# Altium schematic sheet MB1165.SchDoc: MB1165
size A3; DocumentNumber: MB1165; Revision: C.1; SheetNumber: 1; SheetTotal: 17; Project: STM32469I-EVAL
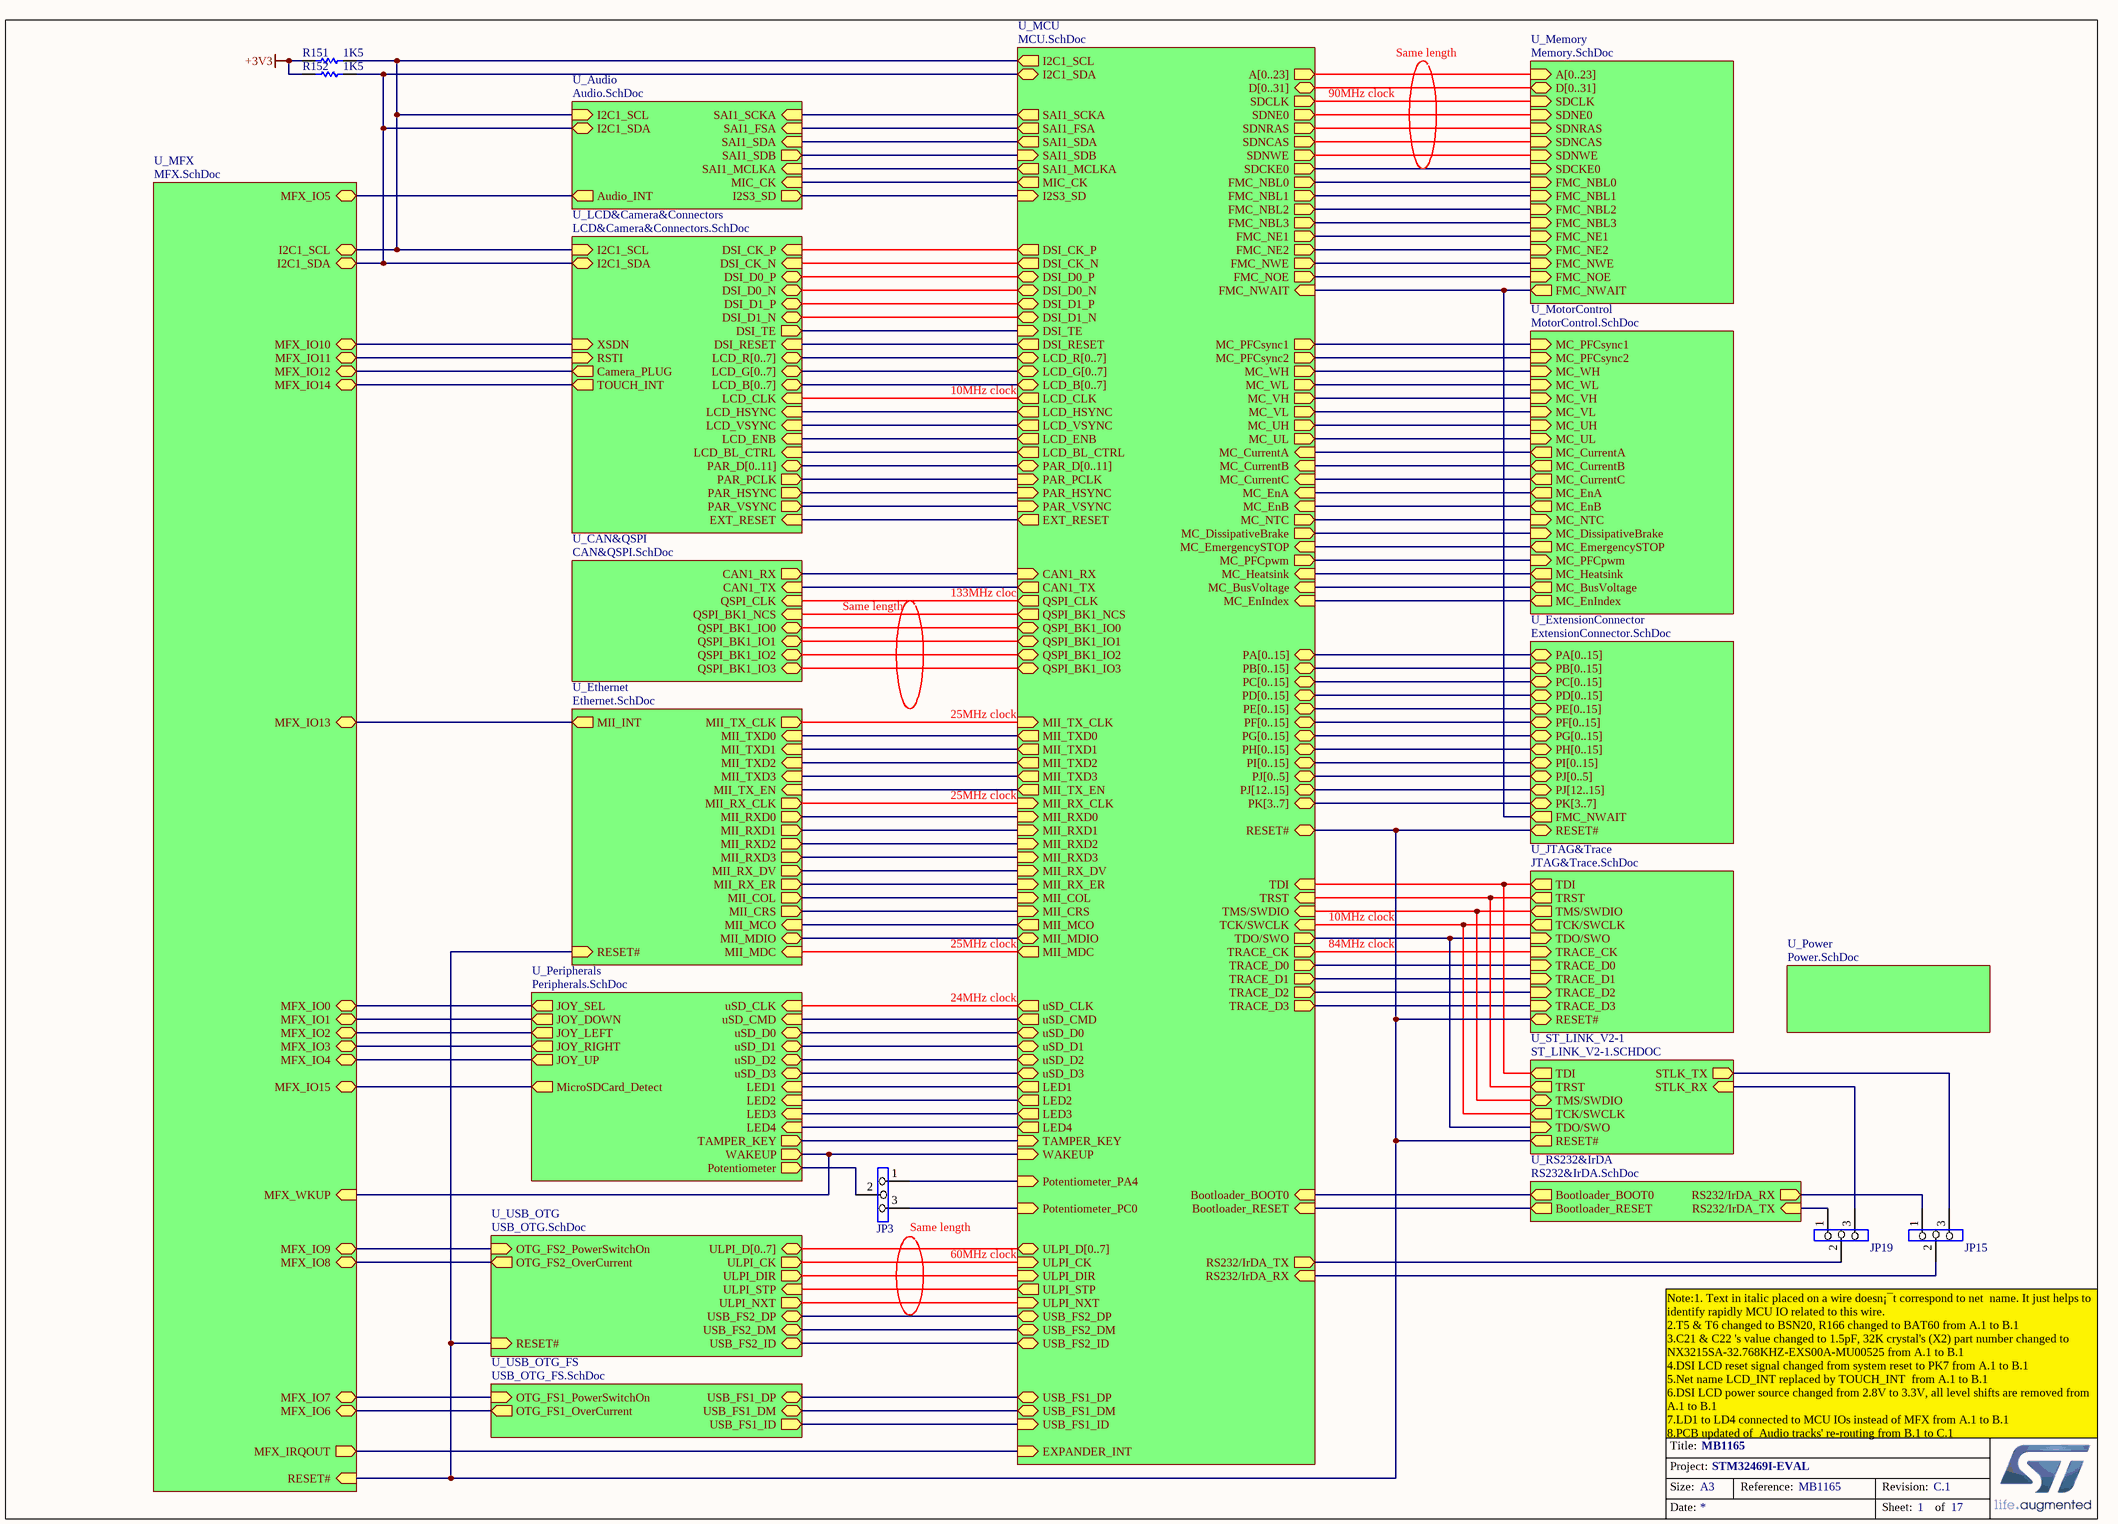
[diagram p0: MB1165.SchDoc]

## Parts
JP3  (no value)  [SIP3]
JP15  (no value)  [SIP3]
JP19  (no value)  [SIP3]
R151  1K5  [0603R]
R152  1K5  [0603R]

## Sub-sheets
U_Audio = Audio.SchDoc: SAI1_SCKA (in), SAI1_FSA (in), SAI1_SDA (in), SAI1_SDB (out), Audio_INT (out), I2C1_SDA (bidir), I2C1_SCL (in), SAI1_MCLKA (in), MIC_CK (in), I2S3_SD (out)
U_CAN&QSPI = CAN&QSPI.SchDoc: CAN1_TX (in), CAN1_RX (out), QSPI_BK1_IO0 (bidir), QSPI_BK1_IO3 (bidir), QSPI_BK1_IO2 (bidir), QSPI_BK1_IO1 (bidir), QSPI_CLK (in), QSPI_BK1_NCS (in)
U_Ethernet = Ethernet.SchDoc: MII_TXD0 (in), MII_TX_EN (in), MII_TX_CLK (out), MII_RXD0 (out), MII_RX_ER (out), MII_RX_DV (out), MII_RX_CLK (out), MII_COL (out), MII_CRS (out), MII_MDC (in), MII_MDIO (bidir), RESET# (in), MII_TXD1 (in), MII_TXD2 (in), MII_TXD3 (in), MII_RXD1 (out), MII_RXD2 (out), MII_RXD3 (out), MII_INT (out), MII_MCO (in)
U_ExtensionConnector = ExtensionConnector.SchDoc: PA[0..15] (bidir), PB[0..15] (bidir), PC[0..15] (bidir), PD[0..15] (bidir), PE[0..15] (bidir), PF[0..15] (bidir), PG[0..15] (bidir), PH[0..15] (bidir), PI[0..15] (bidir), RESET# (bidir), FMC_NWAIT (out), PJ[0..5] (bidir), PK[3..7] (bidir), PJ[12..15] (bidir)
U_JTAG&Trace = JTAG&Trace.SchDoc: TDI (out), RESET# (bidir), TRACE_D3 (in), TRACE_D2 (in), TRACE_D1 (in), TRACE_D0 (in), TRACE_CK (in), TRST (out), TMS/SWDIO (out), TCK/SWCLK (out), TDO/SWO (in)
U_LCD&Camera&Connectors = LCD&Camera&Connectors.SchDoc: LCD_R[0..7] (bidir), LCD_HSYNC (in), LCD_VSYNC (in), LCD_CLK (in), LCD_ENB (in), I2C1_SDA (bidir), I2C1_SCL (in), LCD_B[0..7] (bidir), LCD_G[0..7] (bidir), RSTI (in), XSDN (in), PAR_HSYNC (out), PAR_PCLK (out), PAR_VSYNC (out), PAR_D[0..11] (bidir), TOUCH_INT (out), Camera_PLUG (out), EXT_RESET (in), DSI_CK_P (in), DSI_CK_N (in), DSI_D0_P (bidir), DSI_D0_N (bidir), DSI_D1_P (bidir), DSI_D1_N (bidir), LCD_BL_CTRL (in), DSI_TE (out), DSI_RESET (in)
U_MCU = MCU.SchDoc: PA[0..15] (bidir), PB[0..15] (bidir), PC[0..15] (bidir), PD[0..15] (bidir), PE[0..15] (bidir), PF[0..15] (bidir), PG[0..15] (bidir), PH[0..15] (bidir), PI[0..15] (bidir), MC_EnA (in), MII_RX_CLK (in), MC_EnB (in), MII_MDIO (bidir), MC_EnIndex (in), ULPI_CK (in), MC_EmergencySTOP (in), MII_RX_DV (in), MC_UL (out), LCD_BL_CTRL (out), MC_PFCsync1 (out), RS232/IrDA_TX (out), RS232/IrDA_RX (in), USB_FS1_ID (in), CAN1_RX (in), USB_FS1_DM (bidir), MC_PFCpwm (out), CAN1_TX (out), USB_FS1_DP (bidir), MC_PFCsync2 (out), TMS/SWDIO (in), TCK/SWCLK (in), TDI (in), MC_VL (out), MC_WL (out), TDO/SWO (out), MIC_CK (out), TRST (in), I2C1_SCL (out), MII_TXD3 (out), MC_DissipativeBrake (out), I2C1_SDA (bidir), USB_FS2_ID (bidir), USB_FS2_DM (bidir), USB_FS2_DP (bidir), ULPI_STP (out), MII_MDC (out), MC_CurrentA (in), MII_TXD2 (out), MC_CurrentB (in), MII_TX_CLK (in), MC_CurrentC (in), MII_RXD0 (in), MC_BusVoltage (in), MII_RXD1 (in), MC_Heatsink (in), MC_UH (out), MC_VH (out), uSD_D0 (bidir), MC_WH (out), uSD_D1 (bidir), uSD_D2 (bidir), EXT_RESET (out), uSD_D3 (bidir), uSD_CLK (out), TAMPER_KEY (in), MII_CRS (in), LCD_ENB (out), uSD_CMD (out), FMC_NOE (out), FMC_NWE (out), FMC_NWAIT (in), I2S3_SD (in), FMC_NE1 (out), FMC_NBL3 (out), FMC_NBL2 (out), EXPANDER_INT (in), MII_RX_ER (in), ULPI_DIR (in), LCD_HSYNC (out), LCD_VSYNC (out), LCD_CLK (out), FMC_NBL0 (out), FMC_NBL1 (out), TRACE_CK (out), TRACE_D0 (out), TRACE_D2 (out), TRACE_D1 (out), SAI1_SDA (out), TRACE_D3 (out), SAI1_SDB (in), SAI1_SCKA (out), SAI1_FSA (out), SAI1_MCLKA (out), SDNRAS (out), SDCLK (out), FMC_NE2 (out), MII_TX_EN (out), MC_NTC (out), MII_TXD1 (out), SDNCAS (out), SDCKE0 (out), SDNE0 (out), MII_COL (in), ULPI_NXT (in), SDNWE (out), MII_RXD2 (in), MII_RXD3 (in), LCD_G[0..7] (bidir), LCD_B[0..7] (bidir), D[0..31] (bidir), A[0..23] (out), ULPI_D[0..7] (bidir), RESET# (bidir), PJ[0..5] (bidir), PK[3..7] (bidir), PAR_VSYNC (in), PAR_D[0..11] (bidir), PAR_PCLK (in), PAR_HSYNC (in), MII_MCO (out), LCD_R[0..7] (bidir), Bootloader_BOOT0 (in), QSPI_CLK (out), QSPI_BK1_NCS (out), QSPI_BK1_IO3 (bidir), QSPI_BK1_IO2 (bidir), QSPI_BK1_IO1 (bidir), QSPI_BK1_IO0 (bidir), Bootloader_RESET (in), WAKEUP (in), Potentiometer_PA4 (in), MII_TXD0 (out), Potentiometer_PC0 (in), DSI_TE (in), DSI_CK_P (out), DSI_CK_N (out), DSI_D0_P (bidir), DSI_D0_N (bidir), DSI_D1_P (bidir), DSI_D1_N (bidir), PJ[12..15] (bidir), DSI_RESET (out), LED1 (out), LED2 (out), LED3 (out), LED4 (out)
U_Memory = Memory.SchDoc: FMC_NE1 (in), FMC_NWE (in), FMC_NOE (in), FMC_NWAIT (out), FMC_NBL0 (in), FMC_NBL1 (in), D[0..31] (bidir), A[0..23] (in), SDNCAS (in), SDNWE (in), SDNRAS (in), SDNE0 (in), SDCKE0 (in), SDCLK (in), FMC_NBL3 (in), FMC_NBL2 (in), FMC_NE2 (in)
U_MFX = MFX.SchDoc: MFX_IRQOUT (out), I2C1_SDA (bidir), I2C1_SCL (bidir), MFX_IO5 (bidir), MFX_IO6 (bidir), MFX_IO7 (bidir), MFX_IO8 (bidir), MFX_IO9 (bidir), MFX_IO10 (bidir), MFX_IO11 (bidir), MFX_IO12 (bidir), MFX_IO13 (bidir), MFX_IO14 (bidir), MFX_IO15 (bidir), MFX_WKUP (in), MFX_IO0 (bidir), MFX_IO1 (bidir), MFX_IO2 (bidir), MFX_IO3 (bidir), MFX_IO4 (bidir), RESET# (in)
U_MotorControl = MotorControl.SchDoc: MC_EmergencySTOP (out), MC_CurrentA (out), MC_CurrentB (out), MC_CurrentC (out), MC_PFCsync1 (in), MC_PFCsync2 (in), MC_WL (in), MC_VH (in), MC_VL (in), MC_UH (in), MC_UL (in), MC_WH (in), MC_NTC (in), MC_DissipativeBrake (in), MC_PFCpwm (in), MC_EnA (out), MC_EnB (out), MC_Heatsink (out), MC_BusVoltage (out), MC_EnIndex (out)
U_Peripherals = Peripherals.SchDoc: JOY_SEL (out), JOY_DOWN (out), JOY_LEFT (out), JOY_RIGHT (out), JOY_UP (out), uSD_CLK (in), uSD_CMD (in), uSD_D0 (bidir), uSD_D1 (bidir), uSD_D2 (bidir), uSD_D3 (bidir), MicroSDCard_Detect (out), TAMPER_KEY (out), WAKEUP (out), Potentiometer (out), LED4 (in), LED3 (in), LED1 (in), LED2 (in)
U_Power = Power.SchDoc: no entries
U_RS232&IrDA = RS232&IrDA.SchDoc: RS232/IrDA_TX (in), RS232/IrDA_RX (out), Bootloader_BOOT0 (out), Bootloader_RESET (out)
U_ST_LINK_V2-1 = ST_LINK_V2-1.SCHDOC: STLK_RX (in), STLK_TX (out), TDI (out), TRST (out), TMS/SWDIO (bidir), TCK/SWCLK (out), TDO/SWO (in), RESET# (out)
U_USB_OTG = USB_OTG.SchDoc: ULPI_D[0..7] (bidir), ULPI_CK (out), ULPI_DIR (out), ULPI_NXT (out), ULPI_STP (in), RESET# (in), USB_FS2_DM (bidir), USB_FS2_DP (bidir), OTG_FS2_PowerSwitchOn (in), OTG_FS2_OverCurrent (out), USB_FS2_ID (bidir)
U_USB_OTG_FS = USB_OTG_FS.SchDoc: OTG_FS1_PowerSwitchOn (in), OTG_FS1_OverCurrent (out), USB_FS1_DM (bidir), USB_FS1_DP (bidir), USB_FS1_ID (out)

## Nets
+3V3: R151.1 R152.1
NetJP3_1: JP3.1 ; sheet U_MCU/Potentiometer_PA4
NetJP3_2: JP3.2 ; sheet U_Peripherals/Potentiometer
NetJP3_3: JP3.3 ; sheet U_MCU/Potentiometer_PC0
NetJP15_1: JP15.1 ; sheet U_RS232&IrDA/RS232/IrDA_RX
NetJP15_2: JP15.2 ; sheet U_MCU/RS232/IrDA_RX
NetJP15_3: JP15.3 ; sheet U_ST_LINK_V2-1/STLK_TX
NetJP19_1: JP19.1 ; sheet U_RS232&IrDA/RS232/IrDA_TX
NetJP19_2: JP19.2 ; sheet U_MCU/RS232/IrDA_TX
NetJP19_3: JP19.3 ; sheet U_ST_LINK_V2-1/STLK_RX
NetR151_2: R151.2 ; sheet U_Audio/I2C1_SCL, sheet U_MFX/I2C1_SCL, sheet U_MCU/I2C1_SCL, sheet U_LCD&Camera&Connectors/I2C1_SCL
NetR152_2: R152.2 ; sheet U_Audio/I2C1_SDA, sheet U_MFX/I2C1_SDA, sheet U_MCU/I2C1_SDA, sheet U_LCD&Camera&Connectors/I2C1_SDA
(unnamed): sheet U_Audio/SAI1_SCKA, sheet U_MCU/SAI1_SCKA
(unnamed): sheet U_Audio/SAI1_FSA, sheet U_MCU/SAI1_FSA  [a separate net that carries the same name]
(unnamed): sheet U_Audio/SAI1_SDA, sheet U_MCU/SAI1_SDA  [a separate net that carries the same name]
(unnamed): sheet U_Audio/SAI1_SDB, sheet U_MCU/SAI1_SDB  [a separate net that carries the same name]
(unnamed): sheet U_Audio/Audio_INT, sheet U_MFX/MFX_IO5  [a separate net that carries the same name]
(unnamed): sheet U_Audio/SAI1_MCLKA, sheet U_MCU/SAI1_MCLKA  [a separate net that carries the same name]
(unnamed): sheet U_Audio/MIC_CK, sheet U_MCU/MIC_CK  [a separate net that carries the same name]
(unnamed): sheet U_Audio/I2S3_SD, sheet U_MCU/I2S3_SD  [a separate net that carries the same name]
(unnamed): sheet U_CAN&QSPI/CAN1_TX, sheet U_MCU/CAN1_TX  [a separate net that carries the same name]
(unnamed): sheet U_CAN&QSPI/CAN1_RX, sheet U_MCU/CAN1_RX  [a separate net that carries the same name]
(unnamed): sheet U_CAN&QSPI/QSPI_BK1_IO0, sheet U_MCU/QSPI_BK1_IO0  [a separate net that carries the same name]
(unnamed): sheet U_CAN&QSPI/QSPI_BK1_IO3, sheet U_MCU/QSPI_BK1_IO3  [a separate net that carries the same name]
(unnamed): sheet U_CAN&QSPI/QSPI_BK1_IO2, sheet U_MCU/QSPI_BK1_IO2  [a separate net that carries the same name]
(unnamed): sheet U_CAN&QSPI/QSPI_BK1_IO1, sheet U_MCU/QSPI_BK1_IO1  [a separate net that carries the same name]
(unnamed): sheet U_CAN&QSPI/QSPI_CLK, sheet U_MCU/QSPI_CLK  [a separate net that carries the same name]
(unnamed): sheet U_CAN&QSPI/QSPI_BK1_NCS, sheet U_MCU/QSPI_BK1_NCS  [a separate net that carries the same name]
(unnamed): sheet U_Ethernet/MII_TXD0, sheet U_MCU/MII_TXD0  [a separate net that carries the same name]
(unnamed): sheet U_Ethernet/MII_TX_EN, sheet U_MCU/MII_TX_EN  [a separate net that carries the same name]
(unnamed): sheet U_Ethernet/MII_TX_CLK, sheet U_MCU/MII_TX_CLK  [a separate net that carries the same name]
(unnamed): sheet U_Ethernet/MII_RXD0, sheet U_MCU/MII_RXD0  [a separate net that carries the same name]
(unnamed): sheet U_Ethernet/MII_RX_ER, sheet U_MCU/MII_RX_ER  [a separate net that carries the same name]
(unnamed): sheet U_Ethernet/MII_RX_DV, sheet U_MCU/MII_RX_DV  [a separate net that carries the same name]
(unnamed): sheet U_Ethernet/MII_RX_CLK, sheet U_MCU/MII_RX_CLK  [a separate net that carries the same name]
(unnamed): sheet U_Ethernet/MII_COL, sheet U_MCU/MII_COL  [a separate net that carries the same name]
(unnamed): sheet U_Ethernet/MII_CRS, sheet U_MCU/MII_CRS  [a separate net that carries the same name]
(unnamed): sheet U_Ethernet/MII_MDC, sheet U_MCU/MII_MDC  [a separate net that carries the same name]
(unnamed): sheet U_Ethernet/MII_MDIO, sheet U_MCU/MII_MDIO  [a separate net that carries the same name]
(unnamed): sheet U_Ethernet/RESET#, sheet U_ExtensionConnector/RESET#, sheet U_JTAG&Trace/RESET#, sheet U_ST_LINK_V2-1/RESET#, sheet U_USB_OTG/RESET#, sheet U_MFX/RESET#, sheet U_MCU/RESET#  [a separate net that carries the same name]
(unnamed): sheet U_Ethernet/MII_TXD1, sheet U_MCU/MII_TXD1  [a separate net that carries the same name]
(unnamed): sheet U_Ethernet/MII_TXD2, sheet U_MCU/MII_TXD2  [a separate net that carries the same name]
(unnamed): sheet U_Ethernet/MII_TXD3, sheet U_MCU/MII_TXD3  [a separate net that carries the same name]
(unnamed): sheet U_Ethernet/MII_RXD1, sheet U_MCU/MII_RXD1  [a separate net that carries the same name]
(unnamed): sheet U_Ethernet/MII_RXD2, sheet U_MCU/MII_RXD2  [a separate net that carries the same name]
(unnamed): sheet U_Ethernet/MII_RXD3, sheet U_MCU/MII_RXD3  [a separate net that carries the same name]
(unnamed): sheet U_Ethernet/MII_INT, sheet U_MFX/MFX_IO13  [a separate net that carries the same name]
(unnamed): sheet U_Ethernet/MII_MCO, sheet U_MCU/MII_MCO  [a separate net that carries the same name]
(unnamed): sheet U_ExtensionConnector/FMC_NWAIT, sheet U_Memory/FMC_NWAIT, sheet U_MCU/FMC_NWAIT  [a separate net that carries the same name]
(unnamed): sheet U_JTAG&Trace/TDI, sheet U_ST_LINK_V2-1/TDI, sheet U_MCU/TDI  [a separate net that carries the same name]
(unnamed): sheet U_JTAG&Trace/TRACE_D3, sheet U_MCU/TRACE_D3  [a separate net that carries the same name]
(unnamed): sheet U_JTAG&Trace/TRACE_D2, sheet U_MCU/TRACE_D2  [a separate net that carries the same name]
(unnamed): sheet U_JTAG&Trace/TRACE_D1, sheet U_MCU/TRACE_D1  [a separate net that carries the same name]
(unnamed): sheet U_JTAG&Trace/TRACE_D0, sheet U_MCU/TRACE_D0  [a separate net that carries the same name]
(unnamed): sheet U_JTAG&Trace/TRACE_CK, sheet U_MCU/TRACE_CK  [a separate net that carries the same name]
(unnamed): sheet U_JTAG&Trace/TRST, sheet U_ST_LINK_V2-1/TRST, sheet U_MCU/TRST  [a separate net that carries the same name]
(unnamed): sheet U_JTAG&Trace/TMS/SWDIO, sheet U_ST_LINK_V2-1/TMS/SWDIO, sheet U_MCU/TMS/SWDIO  [a separate net that carries the same name]
(unnamed): sheet U_JTAG&Trace/TCK/SWCLK, sheet U_ST_LINK_V2-1/TCK/SWCLK, sheet U_MCU/TCK/SWCLK  [a separate net that carries the same name]
(unnamed): sheet U_JTAG&Trace/TDO/SWO, sheet U_ST_LINK_V2-1/TDO/SWO, sheet U_MCU/TDO/SWO  [a separate net that carries the same name]
(unnamed): sheet U_Memory/FMC_NE1, sheet U_MCU/FMC_NE1  [a separate net that carries the same name]
(unnamed): sheet U_Memory/FMC_NWE, sheet U_MCU/FMC_NWE  [a separate net that carries the same name]
(unnamed): sheet U_Memory/FMC_NOE, sheet U_MCU/FMC_NOE  [a separate net that carries the same name]
(unnamed): sheet U_Memory/FMC_NBL0, sheet U_MCU/FMC_NBL0  [a separate net that carries the same name]
(unnamed): sheet U_Memory/FMC_NBL1, sheet U_MCU/FMC_NBL1  [a separate net that carries the same name]
(unnamed): sheet U_Memory/SDNCAS, sheet U_MCU/SDNCAS  [a separate net that carries the same name]
(unnamed): sheet U_Memory/SDNWE, sheet U_MCU/SDNWE  [a separate net that carries the same name]
(unnamed): sheet U_Memory/SDNRAS, sheet U_MCU/SDNRAS  [a separate net that carries the same name]
(unnamed): sheet U_Memory/SDNE0, sheet U_MCU/SDNE0  [a separate net that carries the same name]
(unnamed): sheet U_Memory/SDCKE0, sheet U_MCU/SDCKE0  [a separate net that carries the same name]
(unnamed): sheet U_Memory/SDCLK, sheet U_MCU/SDCLK  [a separate net that carries the same name]
(unnamed): sheet U_Memory/FMC_NBL3, sheet U_MCU/FMC_NBL3  [a separate net that carries the same name]
(unnamed): sheet U_Memory/FMC_NBL2, sheet U_MCU/FMC_NBL2  [a separate net that carries the same name]
(unnamed): sheet U_Memory/FMC_NE2, sheet U_MCU/FMC_NE2  [a separate net that carries the same name]
(unnamed): sheet U_MotorControl/MC_EmergencySTOP, sheet U_MCU/MC_EmergencySTOP  [a separate net that carries the same name]
(unnamed): sheet U_MotorControl/MC_CurrentA, sheet U_MCU/MC_CurrentA  [a separate net that carries the same name]
(unnamed): sheet U_MotorControl/MC_CurrentB, sheet U_MCU/MC_CurrentB  [a separate net that carries the same name]
(unnamed): sheet U_MotorControl/MC_CurrentC, sheet U_MCU/MC_CurrentC  [a separate net that carries the same name]
(unnamed): sheet U_MotorControl/MC_PFCsync1, sheet U_MCU/MC_PFCsync1  [a separate net that carries the same name]
(unnamed): sheet U_MotorControl/MC_PFCsync2, sheet U_MCU/MC_PFCsync2  [a separate net that carries the same name]
(unnamed): sheet U_MotorControl/MC_WL, sheet U_MCU/MC_WL  [a separate net that carries the same name]
(unnamed): sheet U_MotorControl/MC_VH, sheet U_MCU/MC_VH  [a separate net that carries the same name]
(unnamed): sheet U_MotorControl/MC_VL, sheet U_MCU/MC_VL  [a separate net that carries the same name]
(unnamed): sheet U_MotorControl/MC_UH, sheet U_MCU/MC_UH  [a separate net that carries the same name]
(unnamed): sheet U_MotorControl/MC_UL, sheet U_MCU/MC_UL  [a separate net that carries the same name]
(unnamed): sheet U_MotorControl/MC_WH, sheet U_MCU/MC_WH  [a separate net that carries the same name]
(unnamed): sheet U_MotorControl/MC_NTC, sheet U_MCU/MC_NTC  [a separate net that carries the same name]
(unnamed): sheet U_MotorControl/MC_DissipativeBrake, sheet U_MCU/MC_DissipativeBrake  [a separate net that carries the same name]
(unnamed): sheet U_MotorControl/MC_PFCpwm, sheet U_MCU/MC_PFCpwm  [a separate net that carries the same name]
(unnamed): sheet U_MotorControl/MC_EnA, sheet U_MCU/MC_EnA  [a separate net that carries the same name]
(unnamed): sheet U_MotorControl/MC_EnB, sheet U_MCU/MC_EnB  [a separate net that carries the same name]
(unnamed): sheet U_MotorControl/MC_Heatsink, sheet U_MCU/MC_Heatsink  [a separate net that carries the same name]
(unnamed): sheet U_MotorControl/MC_BusVoltage, sheet U_MCU/MC_BusVoltage  [a separate net that carries the same name]
(unnamed): sheet U_MotorControl/MC_EnIndex, sheet U_MCU/MC_EnIndex  [a separate net that carries the same name]
(unnamed): sheet U_RS232&IrDA/Bootloader_BOOT0, sheet U_MCU/Bootloader_BOOT0  [a separate net that carries the same name]
(unnamed): sheet U_RS232&IrDA/Bootloader_RESET, sheet U_MCU/Bootloader_RESET  [a separate net that carries the same name]
(unnamed): sheet U_USB_OTG/ULPI_CK, sheet U_MCU/ULPI_CK  [a separate net that carries the same name]
(unnamed): sheet U_USB_OTG/ULPI_DIR, sheet U_MCU/ULPI_DIR  [a separate net that carries the same name]
(unnamed): sheet U_USB_OTG/ULPI_NXT, sheet U_MCU/ULPI_NXT  [a separate net that carries the same name]
(unnamed): sheet U_USB_OTG/ULPI_STP, sheet U_MCU/ULPI_STP  [a separate net that carries the same name]
(unnamed): sheet U_USB_OTG/USB_FS2_DM, sheet U_MCU/USB_FS2_DM  [a separate net that carries the same name]
(unnamed): sheet U_USB_OTG/USB_FS2_DP, sheet U_MCU/USB_FS2_DP  [a separate net that carries the same name]
(unnamed): sheet U_USB_OTG/OTG_FS2_PowerSwitchOn, sheet U_MFX/MFX_IO9  [a separate net that carries the same name]
(unnamed): sheet U_USB_OTG/OTG_FS2_OverCurrent, sheet U_MFX/MFX_IO8  [a separate net that carries the same name]
(unnamed): sheet U_USB_OTG/USB_FS2_ID, sheet U_MCU/USB_FS2_ID  [a separate net that carries the same name]
(unnamed): sheet U_USB_OTG_FS/OTG_FS1_PowerSwitchOn, sheet U_MFX/MFX_IO7  [a separate net that carries the same name]
(unnamed): sheet U_USB_OTG_FS/OTG_FS1_OverCurrent, sheet U_MFX/MFX_IO6  [a separate net that carries the same name]
(unnamed): sheet U_USB_OTG_FS/USB_FS1_DM, sheet U_MCU/USB_FS1_DM  [a separate net that carries the same name]
(unnamed): sheet U_USB_OTG_FS/USB_FS1_DP, sheet U_MCU/USB_FS1_DP  [a separate net that carries the same name]
(unnamed): sheet U_USB_OTG_FS/USB_FS1_ID, sheet U_MCU/USB_FS1_ID  [a separate net that carries the same name]
(unnamed): sheet U_MFX/MFX_IRQOUT, sheet U_MCU/EXPANDER_INT  [a separate net that carries the same name]
(unnamed): sheet U_MFX/MFX_IO10, sheet U_LCD&Camera&Connectors/XSDN  [a separate net that carries the same name]
(unnamed): sheet U_MFX/MFX_IO11, sheet U_LCD&Camera&Connectors/RSTI  [a separate net that carries the same name]
(unnamed): sheet U_MFX/MFX_IO12, sheet U_LCD&Camera&Connectors/Camera_PLUG  [a separate net that carries the same name]
(unnamed): sheet U_MFX/MFX_IO14, sheet U_LCD&Camera&Connectors/TOUCH_INT  [a separate net that carries the same name]
(unnamed): sheet U_MFX/MFX_IO15, sheet U_Peripherals/MicroSDCard_Detect  [a separate net that carries the same name]
(unnamed): sheet U_MFX/MFX_WKUP, sheet U_MCU/WAKEUP, sheet U_Peripherals/WAKEUP  [a separate net that carries the same name]
(unnamed): sheet U_MFX/MFX_IO0, sheet U_Peripherals/JOY_SEL  [a separate net that carries the same name]
(unnamed): sheet U_MFX/MFX_IO1, sheet U_Peripherals/JOY_DOWN  [a separate net that carries the same name]
(unnamed): sheet U_MFX/MFX_IO2, sheet U_Peripherals/JOY_LEFT  [a separate net that carries the same name]
(unnamed): sheet U_MFX/MFX_IO3, sheet U_Peripherals/JOY_RIGHT  [a separate net that carries the same name]
(unnamed): sheet U_MFX/MFX_IO4, sheet U_Peripherals/JOY_UP  [a separate net that carries the same name]
(unnamed): sheet U_MCU/LCD_BL_CTRL, sheet U_LCD&Camera&Connectors/LCD_BL_CTRL  [a separate net that carries the same name]
(unnamed): sheet U_MCU/uSD_D0, sheet U_Peripherals/uSD_D0  [a separate net that carries the same name]
(unnamed): sheet U_MCU/uSD_D1, sheet U_Peripherals/uSD_D1  [a separate net that carries the same name]
(unnamed): sheet U_MCU/uSD_D2, sheet U_Peripherals/uSD_D2  [a separate net that carries the same name]
(unnamed): sheet U_MCU/EXT_RESET, sheet U_LCD&Camera&Connectors/EXT_RESET  [a separate net that carries the same name]
(unnamed): sheet U_MCU/uSD_D3, sheet U_Peripherals/uSD_D3  [a separate net that carries the same name]
(unnamed): sheet U_MCU/uSD_CLK, sheet U_Peripherals/uSD_CLK  [a separate net that carries the same name]
(unnamed): sheet U_MCU/TAMPER_KEY, sheet U_Peripherals/TAMPER_KEY  [a separate net that carries the same name]
(unnamed): sheet U_MCU/LCD_ENB, sheet U_LCD&Camera&Connectors/LCD_ENB  [a separate net that carries the same name]
(unnamed): sheet U_MCU/uSD_CMD, sheet U_Peripherals/uSD_CMD  [a separate net that carries the same name]
(unnamed): sheet U_MCU/LCD_HSYNC, sheet U_LCD&Camera&Connectors/LCD_HSYNC  [a separate net that carries the same name]
(unnamed): sheet U_MCU/LCD_VSYNC, sheet U_LCD&Camera&Connectors/LCD_VSYNC  [a separate net that carries the same name]
(unnamed): sheet U_MCU/LCD_CLK, sheet U_LCD&Camera&Connectors/LCD_CLK  [a separate net that carries the same name]
(unnamed): sheet U_MCU/PAR_VSYNC, sheet U_LCD&Camera&Connectors/PAR_VSYNC  [a separate net that carries the same name]
(unnamed): sheet U_MCU/PAR_PCLK, sheet U_LCD&Camera&Connectors/PAR_PCLK  [a separate net that carries the same name]
(unnamed): sheet U_MCU/PAR_HSYNC, sheet U_LCD&Camera&Connectors/PAR_HSYNC  [a separate net that carries the same name]
(unnamed): sheet U_MCU/DSI_TE, sheet U_LCD&Camera&Connectors/DSI_TE  [a separate net that carries the same name]
(unnamed): sheet U_MCU/DSI_CK_P, sheet U_LCD&Camera&Connectors/DSI_CK_P  [a separate net that carries the same name]
(unnamed): sheet U_MCU/DSI_CK_N, sheet U_LCD&Camera&Connectors/DSI_CK_N  [a separate net that carries the same name]
(unnamed): sheet U_MCU/DSI_D0_P, sheet U_LCD&Camera&Connectors/DSI_D0_P  [a separate net that carries the same name]
(unnamed): sheet U_MCU/DSI_D0_N, sheet U_LCD&Camera&Connectors/DSI_D0_N  [a separate net that carries the same name]
(unnamed): sheet U_MCU/DSI_D1_P, sheet U_LCD&Camera&Connectors/DSI_D1_P  [a separate net that carries the same name]
(unnamed): sheet U_MCU/DSI_D1_N, sheet U_LCD&Camera&Connectors/DSI_D1_N  [a separate net that carries the same name]
(unnamed): sheet U_MCU/DSI_RESET, sheet U_LCD&Camera&Connectors/DSI_RESET  [a separate net that carries the same name]
(unnamed): sheet U_MCU/LED1, sheet U_Peripherals/LED1  [a separate net that carries the same name]
(unnamed): sheet U_MCU/LED2, sheet U_Peripherals/LED2  [a separate net that carries the same name]
(unnamed): sheet U_MCU/LED3, sheet U_Peripherals/LED3  [a separate net that carries the same name]
(unnamed): sheet U_MCU/LED4, sheet U_Peripherals/LED4  [a separate net that carries the same name]

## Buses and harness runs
bus sheet U_ExtensionConnector/PA[0..15] = sheet U_MCU/PA[0..15]
bus sheet U_ExtensionConnector/PB[0..15] = sheet U_MCU/PB[0..15]
bus sheet U_ExtensionConnector/PC[0..15] = sheet U_MCU/PC[0..15]
bus sheet U_ExtensionConnector/PD[0..15] = sheet U_MCU/PD[0..15]
bus sheet U_ExtensionConnector/PE[0..15] = sheet U_MCU/PE[0..15]
bus sheet U_ExtensionConnector/PF[0..15] = sheet U_MCU/PF[0..15]
bus sheet U_ExtensionConnector/PG[0..15] = sheet U_MCU/PG[0..15]
bus sheet U_ExtensionConnector/PH[0..15] = sheet U_MCU/PH[0..15]
bus sheet U_ExtensionConnector/PI[0..15] = sheet U_MCU/PI[0..15]
bus sheet U_ExtensionConnector/PJ[0..5] = sheet U_MCU/PJ[0..5]
bus sheet U_ExtensionConnector/PJ[12..15] = sheet U_MCU/PJ[12..15]
bus sheet U_ExtensionConnector/PK[3..7] = sheet U_MCU/PK[3..7]
bus sheet U_LCD&Camera&Connectors/LCD_B[0..7] = sheet U_MCU/LCD_B[0..7]
bus sheet U_LCD&Camera&Connectors/LCD_G[0..7] = sheet U_MCU/LCD_G[0..7]
bus sheet U_LCD&Camera&Connectors/LCD_R[0..7] = sheet U_MCU/LCD_R[0..7]
bus sheet U_LCD&Camera&Connectors/PAR_D[0..11] = sheet U_MCU/PAR_D[0..11]
bus sheet U_MCU/A[0..23] = sheet U_Memory/A[0..23]
bus sheet U_MCU/D[0..31] = sheet U_Memory/D[0..31]
bus sheet U_MCU/ULPI_D[0..7] = sheet U_USB_OTG/ULPI_D[0..7]

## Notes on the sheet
- Same length
- 90MHz clock
- 10MHz clock
- 133MHz clock
- 25MHz clock
- 24MHz clock
- 84MHz clock
- (near JP3) Same length
- 60MHz clock
- Note:1. Text in italic placed on a wire doesn¡¯t correspond to net  name. It just helps to identify rapidly MCU IO related to this wire.
  2.T5 & T6 changed to BSN20, R166 changed to BAT60 from A.1 to B.1
  3.C21 & C22 's value changed to 1.5pF, 32K crystal's (X2) part number changed to NX3215SA-32.768KHZ-EXS00A-MU00525 from A.1 to B.1
  4.DSI LCD reset signal changed from system reset to PK7 from A.1 to B.1
  5.Net name LCD_INT replaced by TOUCH_INT  from A.1 to B.1
  6.DSI LCD power source changed from 2.8V to 3.3V, all level shifts are removed from A.1 to B.1
  7.LD1 to LD4 connected to MCU IOs instead of MFX from A.1 to B.1
  8.PCB updated of  Audio tracks' re-routing from B.1 to C.1

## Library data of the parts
JP3 JP15 JP19 = Jumper3
R151 R152 = Res1: Resistor; Value: 1K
